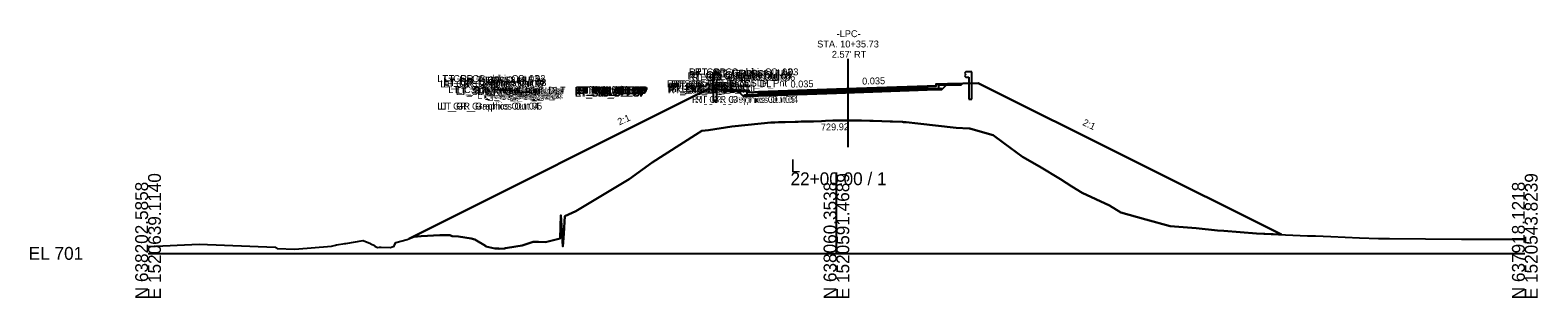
# Model space of a CAD drawing. Extents: x -26 to 3903, y -10 to 9531.
# Drawn here: x 974.3 to 1302.8, y 1990.3 to 2048.6 of the extents above; entities that cross this region are included whole.
import ezdxf

# ---------------------------------------------------------------- set-up
doc = ezdxf.new("R2010")
doc.units = 0
for name, color, linetype in [('Default', 7, 'Continuous'), ('Exist Cross Section Cell', 7, 'Continuous'), ('Exist XS Center Line Elevation Label', 7, 'Continuous'), ('Exist XS Ground Line', 7, 'Continuous'), ('Old_Level_63', 7, 'Continuous'), ('Prop CMT Conc Surface', 7, 'Continuous'), ('Prop CMT Guardrail Graphics', 7, 'Continuous'), ('Prop CMT Pvmt Course 1', 7, 'Continuous'), ('Prop CMT Pvmt Course 1 CG', 7, 'Continuous'), ('Prop CMT Pvmt Course 2', 7, 'Continuous'), ('Prop CMT Pvmt Course 3', 7, 'Continuous'), ('Prop CMT Pvmt Surface', 7, 'Continuous'), ('Prop CMT Slope Grass', 7, 'Continuous'), ('Prop CMT Subgrade Earthwork', 7, 'Continuous'), ('Prop XS Earthwork Shape', 7, 'Continuous'), ('Prop XS Finish Grade Concrete', 7, 'Continuous'), ('Prop XS SE Text', 7, 'Continuous'), ('Prop XS Side Slope Text', 7, 'Continuous')]:
    doc.layers.add(name, color=color, linetype=linetype)

msp = doc.modelspace()

# ---------------------------------------------------------------- linework, layer by layer
at = {"layer": 'Exist Cross Section Cell'}
for p, q in [((1150, 2000), (1150, 2017.66)), ((1000, 2000), (1150, 2000)), ((1150, 2000), (1300, 2000))]:
    msp.add_line(p, q, dxfattribs=at)
at = {"layer": 'Exist XS Ground Line'}
msp.add_lwpolyline([(1000, 2001.52), (1011.14, 2001.98), (1027.72, 2001.34), (1028.14, 2001.07), (1031.96, 2000.89), (1039.99, 2001.56), (1040.83, 2001.78), (1041.03, 2001.83), (1042.86, 2002.16), (1043.11, 2002.18), (1046.84, 2002.77), (1048.5, 2002.18), (1048.53, 2002.1), (1049.34, 2001.7), (1049.43, 2001.58), (1050.03, 2001.3), (1050.43, 2001.36), (1050.8, 2001.34), (1052.8, 2001.26), (1053.22, 2001.4), (1053.66, 2001.58), (1053.77, 2002.01), (1054.01, 2002.34), (1056.48, 2003.06), (1057.92, 2003.64), (1059.52, 2003.78), (1063.59, 2004), (1065.76, 2003.99), (1066.23, 2003.77), (1067.64, 2003.65), (1070.4, 2003.26), (1071.19, 2003.01), (1073.51, 2001.61), (1073.62, 2001.51), (1075.56, 2001.08), (1075.62, 2001.06), (1076.34, 2001.04), (1076.54, 2001.01), (1077.67, 2001.08), (1077.91, 2001.11), (1080.17, 2001.5), (1081.51, 2001.69), (1083.9, 2002.52), (1084.62, 2002.55), (1085.1, 2002.53), (1086.57, 2002.46), (1089.77, 2003.21), (1089.96, 2008.32), (1090.28, 2002.72), (1090.35, 2002.75), (1090.36, 2001.52), (1090.47, 2002.62), (1090.6, 2004.31), (1090.81, 2008.09), (1093.19, 2009.2), (1104.87, 2016.16), (1109.83, 2019.84), (1119.3, 2025.81), (1120.7, 2026.69), (1122.13, 2026.88), (1127.21, 2027.65), (1130.8, 2028.03), (1135.74, 2028.51), (1136.24, 2028.52), (1136.54, 2028.53), (1137.39, 2028.56), (1138.81, 2028.61), (1141.02, 2028.68), (1141.46, 2028.69), (1141.68, 2028.7), (1142.33, 2028.71), (1144.09, 2028.74), (1144.97, 2028.77), (1146.72, 2028.82), (1147.59, 2028.85), (1149.25, 2028.93), (1149.39, 2028.94), (1149.43, 2028.93), (1150.17, 2028.93), (1150.44, 2028.94), (1151.97, 2028.94), (1153.49, 2028.93), (1154.61, 2028.93), (1155.47, 2028.93), (1157.25, 2028.91), (1157.45, 2028.91), (1158.03, 2028.88), (1159.88, 2028.8), (1161.7, 2028.75), (1162.04, 2028.74), (1162.04, 2028.74), (1162.18, 2028.74), (1164.37, 2028.64), (1164.61, 2028.62), (1164.63, 2028.62), (1165.22, 2028.6), (1167.75, 2028.31), (1176.1, 2027.33), (1178.94, 2027.21), (1179.09, 2027.21), (1182.85, 2026.13), (1184.14, 2025.77), (1186.37, 2024.09), (1190.54, 2021.03), (1194.28, 2018.93), (1198.79, 2016.17), (1201.32, 2014.58), (1203.54, 2013.18), (1209.52, 2010.41), (1211.99, 2008.93), (1217.39, 2007.37), (1222.72, 2005.91), (1228.37, 2005.49), (1233.07, 2004.98), (1234.41, 2004.89), (1241.52, 2004.31), (1252.66, 2003.84), (1254.38, 2003.79), (1257.74, 2003.66), (1263.96, 2003.36), (1268.13, 2003.27), (1269.35, 2003.25), (1270.52, 2003.24), (1286.18, 2003.13), (1291.49, 2003.09), (1300, 2003.09)], dxfattribs=at)
at = {"layer": 'Old_Level_63'}
for p, q in [((1171.75, 2036.95), (1171.75, 2036.45)), ((1131, 2035.02), (1131, 2035.52)), ((1133, 2035.17), (1131, 2035.02)), ((1171.75, 2036.45), (1169.75, 2036.46))]:
    msp.add_line(p, q, dxfattribs=at)
for points in [[(1172.25, 2036.95), (1172.25, 2035.96), (1169.75, 2035.87)], [(1177.24, 2036.73), (1177.25, 2037.05)], [(1125.5, 2035.28), (1125.5, 2035.61)], [(1130.5, 2035.18), (1125.5, 2035.28)], [(1130.5, 2035.52), (1130.5, 2034.5), (1133, 2034.59)], [(1130.5, 2035.52), (1130.5, 2035.19)], [(1133, 2034.59), (1133, 2035.17)], [(1169.75, 2035.87), (1169.75, 2036.46)], [(1172.25, 2036.63), (1177.24, 2036.73)]]:
    msp.add_lwpolyline(points, dxfattribs=at)
at = {"layer": 'Prop CMT Conc Surface'}
for points in [[(1121.71, 2036.43), (1121.71, 2036.93), (1122.21, 2036.93)], [(1171.71, 2036.43), (1171.71, 2036.93), (1172.21, 2036.93)], [(1080.47, 2035.51), (1075.47, 2035.61)], [(1080.97, 2035), (1080.97, 2035.5), (1080.47, 2035.5)], [(1082.97, 2035.15), (1080.97, 2035)], [(1119.71, 2036.44), (1121.71, 2036.43)], [(1130.47, 2035.51), (1125.47, 2035.61)], [(1130.97, 2035), (1130.97, 2035.5), (1130.47, 2035.5)], [(1132.97, 2035.15), (1130.97, 2035)], [(1169.71, 2036.44), (1171.71, 2036.43)]]:
    msp.add_lwpolyline(points, dxfattribs=at)
at = {"layer": 'Prop CMT Guardrail Graphics'}
for points in [[(1123.21, 2033.08), (1123.21, 2039.08)], [(1123.21, 2039.08), (1124.54, 2039.08), (1124.81, 2038.78)], [(1124.81, 2038.2), (1124.54, 2037.91), (1123.88, 2037.91)], [(1123.88, 2037.91), (1123.88, 2033.08)], [(1124.81, 2038.78), (1124.54, 2038.49)], [(1124.54, 2038.49), (1124.81, 2038.2)], [(1179.5, 2039.6), (1178.16, 2039.6), (1177.89, 2039.3)], [(1177.89, 2039.3), (1178.16, 2039.01)], [(1178.16, 2039.01), (1177.89, 2038.72)], [(1177.89, 2038.72), (1178.16, 2038.43), (1178.83, 2038.43)], [(1178.83, 2038.43), (1178.83, 2033.6)], [(1179.5, 2033.6), (1179.5, 2039.6)], [(1123.88, 2033.08), (1123.21, 2033.08)], [(1178.83, 2033.6), (1179.5, 2033.6)]]:
    msp.add_lwpolyline(points, dxfattribs=at)
at = {"layer": 'Prop CMT Pvmt Course 1'}
for q in [(1133, 2035.17), (1169.75, 2036.46)]:
    msp.add_line((1150, 2035.76), q, dxfattribs=at)
for points in [[(1133, 2034.92), (1150, 2035.51)], [(1133, 2035.17), (1133, 2034.92)], [(1169.75, 2036.21), (1150, 2035.51)], [(1150, 2035.51), (1150, 2035.76)], [(1150, 2035.51), (1150, 2035.76)], [(1169.75, 2036.46), (1169.75, 2036.21)]]:
    msp.add_lwpolyline(points, dxfattribs=at)
msp.add_lwpolyline([(1150, 2035.51), (1150, 2035.64), (1150, 2035.64), (1150, 2035.51)], close=True, dxfattribs=at)
msp.add_lwpolyline([(1150, 2035.51), (1150, 2035.64), (1150, 2035.64), (1150, 2035.51)], close=True, dxfattribs=at)
at = {"layer": 'Prop CMT Pvmt Course 1 CG'}
for points in [[(1133, 2034.59), (1130, 2034.48), (1129.74, 2034.22)], [(1129.74, 2034.22), (1133, 2034.34)], [(1133, 2034.34), (1133, 2034.59)], [(1169.75, 2035.87), (1172.75, 2035.98), (1172.99, 2035.74)], [(1169.75, 2035.62), (1169.75, 2035.87)], [(1172.99, 2035.74), (1169.75, 2035.62)]]:
    msp.add_lwpolyline(points, dxfattribs=at)
at = {"layer": 'Prop CMT Pvmt Course 2'}
for points in [[(1150, 2035.51), (1133, 2034.92)], [(1133, 2034.59), (1150, 2035.18)], [(1133, 2034.92), (1133, 2034.59)], [(1150, 2035.51), (1169.75, 2036.21)], [(1169.75, 2035.87), (1150, 2035.18)], [(1150, 2035.18), (1150, 2035.51)], [(1150, 2035.18), (1150, 2035.51)], [(1169.75, 2036.21), (1169.75, 2035.87)]]:
    msp.add_lwpolyline(points, dxfattribs=at)
at = {"layer": 'Prop CMT Pvmt Course 3'}
for points in [[(1150, 2035.18), (1133, 2034.59)], [(1133, 2034.34), (1150, 2034.93)], [(1133, 2034.59), (1133, 2034.34)], [(1150, 2035.18), (1169.75, 2035.87)], [(1169.75, 2035.62), (1150, 2034.93)], [(1150, 2034.93), (1150, 2035.18)], [(1150, 2034.93), (1150, 2035.18)], [(1169.75, 2035.87), (1169.75, 2035.62)]]:
    msp.add_lwpolyline(points, dxfattribs=at)
at = {"layer": 'Prop CMT Pvmt Surface'}
for p, q in [((1150, 2035.76), (1133, 2035.17)), ((1169.75, 2036.46), (1150, 2035.76))]:
    msp.add_line(p, q, dxfattribs=at)
for points in [[(1150, 2035.76), (1133, 2035.17)], [(1150, 2035.76), (1169.75, 2036.46)]]:
    msp.add_lwpolyline(points, dxfattribs=at)
at = {"layer": 'Prop CMT Slope Grass'}
msp.add_line((1180.89, 2037.12), (1246.97, 2004.08), dxfattribs=at)
for points in [[(1172.25, 2036.95), (1180.89, 2037.12)], [(1121.81, 2035.7), (1056.82, 2003.2)], [(1130.5, 2035.52), (1121.81, 2035.69)]]:
    msp.add_lwpolyline(points, dxfattribs=at)
at = {"layer": 'Prop CMT Subgrade Earthwork'}
for points in [[(1169.75, 2035.62), (1172.99, 2035.74), (1174.24, 2036.99)], [(1133, 2034.34), (1129.74, 2034.22), (1128.4, 2035.56)], [(1150, 2034.93), (1133, 2034.34)], [(1150, 2034.93), (1169.75, 2035.62)]]:
    msp.add_lwpolyline(points, dxfattribs=at)
at = {"layer": 'Prop XS Earthwork Shape'}
for points in [[(1172.99, 2035.74), (1174.22, 2036.97), (1180.89, 2037.12), (1246.97, 2004.08), (1241.52, 2004.31), (1234.41, 2004.89), (1233.07, 2004.98), (1228.37, 2005.49), (1222.72, 2005.91), (1217.39, 2007.37), (1211.99, 2008.93), (1209.52, 2010.41), (1203.54, 2013.18), (1201.32, 2014.58), (1198.79, 2016.17), (1194.28, 2018.93), (1190.54, 2021.03), (1186.37, 2024.09), (1184.14, 2025.77), (1182.85, 2026.13), (1179.09, 2027.21), (1178.94, 2027.21), (1176.1, 2027.33), (1167.75, 2028.31), (1165.22, 2028.6), (1164.63, 2028.62), (1164.37, 2028.64), (1162.18, 2028.74), (1162.04, 2028.74), (1161.7, 2028.75), (1159.88, 2028.8), (1158.03, 2028.88), (1157.45, 2028.91), (1157.25, 2028.91), (1155.47, 2028.93), (1154.61, 2028.93), (1153.49, 2028.93), (1151.97, 2028.94), (1150.44, 2028.94), (1150.17, 2028.93), (1149.43, 2028.93), (1149.25, 2028.93), (1147.59, 2028.85), (1146.72, 2028.82), (1144.97, 2028.77), (1144.09, 2028.74), (1142.33, 2028.71), (1141.68, 2028.7), (1141.46, 2028.69), (1141.02, 2028.68), (1138.81, 2028.61), (1137.39, 2028.56), (1136.54, 2028.53), (1136.24, 2028.52), (1135.74, 2028.51), (1130.8, 2028.03), (1127.21, 2027.65), (1122.13, 2026.88), (1120.7, 2026.69), (1119.3, 2025.81), (1109.83, 2019.84), (1104.87, 2016.16), (1093.19, 2009.2), (1090.81, 2008.09), (1090.6, 2004.31), (1090.36, 2001.52), (1090.28, 2002.72), (1089.96, 2008.32), (1089.77, 2003.21), (1086.57, 2002.46), (1085.1, 2002.53), (1084.62, 2002.55), (1083.9, 2002.52), (1081.51, 2001.69), (1080.17, 2001.5), (1077.91, 2001.11), (1077.67, 2001.08), (1076.54, 2001.01), (1076.34, 2001.04), (1075.56, 2001.08), (1073.62, 2001.51), (1073.51, 2001.61), (1071.19, 2003.01), (1070.4, 2003.26), (1067.64, 2003.65), (1066.23, 2003.77), (1065.76, 2003.99), (1063.59, 2004), (1059.52, 2003.78), (1057.92, 2003.64), (1056.82, 2003.2), (1121.81, 2035.7), (1125.47, 2035.61), (1128.42, 2035.55), (1129.74, 2034.22), (1133, 2034.34), (1150, 2034.93), (1169.75, 2035.62)], [(1150, 2034.93), (1133, 2034.34), (1129.74, 2034.22), (1128.42, 2035.55), (1125.47, 2035.61), (1121.81, 2035.7), (1056.82, 2003.2), (1057.92, 2003.64), (1059.52, 2003.78), (1063.59, 2004), (1065.76, 2003.99), (1066.23, 2003.77), (1067.64, 2003.65), (1070.4, 2003.26), (1071.19, 2003.01), (1073.51, 2001.61), (1073.62, 2001.51), (1075.56, 2001.08), (1076.34, 2001.04), (1076.54, 2001.01), (1077.67, 2001.08), (1077.91, 2001.11), (1080.17, 2001.5), (1081.51, 2001.69), (1083.9, 2002.52), (1084.62, 2002.55), (1085.1, 2002.53), (1086.57, 2002.46), (1089.77, 2003.21), (1089.96, 2008.32), (1090.28, 2002.72), (1090.36, 2001.52), (1090.6, 2004.31), (1090.81, 2008.09), (1093.19, 2009.2), (1104.87, 2016.16), (1109.83, 2019.84), (1119.3, 2025.81), (1120.7, 2026.69), (1122.13, 2026.88), (1127.21, 2027.65), (1130.8, 2028.03), (1135.74, 2028.51), (1136.24, 2028.52), (1136.54, 2028.53), (1137.39, 2028.56), (1138.81, 2028.61), (1141.02, 2028.68), (1141.46, 2028.69), (1141.68, 2028.7), (1142.33, 2028.71), (1144.09, 2028.74), (1144.97, 2028.77), (1146.72, 2028.82), (1147.59, 2028.85), (1149.25, 2028.93), (1149.43, 2028.93), (1150.17, 2028.93), (1150.44, 2028.94), (1151.97, 2028.94), (1153.49, 2028.93), (1154.61, 2028.93), (1155.47, 2028.93), (1157.25, 2028.91), (1157.45, 2028.91), (1158.03, 2028.88), (1159.88, 2028.8), (1161.7, 2028.75), (1162.04, 2028.74), (1162.18, 2028.74), (1164.37, 2028.64), (1164.63, 2028.62), (1165.22, 2028.6), (1167.75, 2028.31), (1176.1, 2027.33), (1178.94, 2027.21), (1179.09, 2027.21), (1182.85, 2026.13), (1184.14, 2025.77), (1186.37, 2024.09), (1190.54, 2021.03), (1194.28, 2018.93), (1198.79, 2016.17), (1201.32, 2014.58), (1203.54, 2013.18), (1209.52, 2010.41), (1211.99, 2008.93), (1217.39, 2007.37), (1222.72, 2005.91), (1228.37, 2005.49), (1233.07, 2004.98), (1234.41, 2004.89), (1241.52, 2004.31), (1246.97, 2004.08), (1180.89, 2037.12), (1174.22, 2036.97), (1172.99, 2035.74), (1169.75, 2035.62)]]:
    msp.add_lwpolyline(points, close=True, dxfattribs=at)
at = {"layer": 'Prop XS Finish Grade Concrete'}
for points in [[(1169.75, 2036.46), (1171.75, 2036.45), (1171.75, 2036.95), (1172.25, 2036.95)], [(1133, 2035.17), (1131, 2035.02), (1131, 2035.52), (1130.5, 2035.52)]]:
    msp.add_lwpolyline(points, dxfattribs=at)
at = {"layer": 'Prop XS SE Text'}
msp.add_line((1152.57, 2023.13), (1152.57, 2042.42), dxfattribs=at)

# ---------------------------------------------------------------- texts
at = {"layer": 'Default'}
msp.add_text('-', height=0.0001, dxfattribs=at).set_placement((1000.03, 2000.02))
at = {"layer": 'Exist Cross Section Cell'}
for s, p in [('E 1520639.1140', (1002.8, 1990)), ('E 1520591.4689', (1152.8, 1990)), ('E 1520543.8239', (1302.8, 1990)), ('N 638202.5858', (1000, 1990)), ('N 638060.3538', (1150, 1990)), ('N 637918.1218', (1300, 1990))]:
    msp.add_text(s, height=2.8, rotation=90, dxfattribs=at).set_placement(p)
for s, p in [('22+00.00 / 1', (1140, 2014.86)), ('L', (1140, 2017.66)), ('EL 701', (974, 1998.6))]:
    msp.add_text(s, height=2.8, dxfattribs=at).set_placement(p)
at = {"layer": 'Exist XS Center Line Elevation Label'}
msp.add_text('729.92', height=1.5, rotation=0.8401, dxfattribs=at).set_placement((1146.61, 2026.77))
at = {"layer": 'Prop CMT Conc Surface'}
for s, p in [('RT_GR_Graphics Out 02', (1117.88, 2038.8)), ('RT_GR_Graphics Out 03', (1119.19, 2038.8)), ('LT_GR_Graphics Out 03', (1063.04, 2037.35)), ('LT_GR_Graphics Out 06', (1063.68, 2036.19)), ('LT_GR_Graphics Out 07', (1064.33, 2036.19)), ('LT_GR_Graphics Out 09', (1064.35, 2036.77)), ('LT_GR_Graphics Out 02', (1064.39, 2037.35)), ('LT_GR_Graphics Out 08', (1064.62, 2036.48)), ('LT_GR_Out', (1070.47, 2037.06)), ('RT_Sub_Trench_Out_DLT', (1113.09, 2036.22)), ('RT_PV2_OEOT', (1113.24, 2035.44)), ('RT_PV1_OEOT', (1113.42, 2035.69)), ('RT_CG_Top_Face', (1114.01, 2036.18)), ('RT_CG_Top_Gut', (1114.4, 2035.68)), ('RT_CG_Top_BOC', (1114.48, 2036.18)), ('RT_GR_Graphics Out 08', (1117.56, 2037.93)), ('RT_GR_Graphics Out 07', (1117.82, 2037.64)), ('RT_GR_Graphics Out 09', (1117.84, 2038.22)), ('RT_GR_Graphics Out 06', (1118.5, 2037.64)), ('RT_GR_Out', (1123.42, 2038.51)), ('RT_CSLP_Pnt', (1126.07, 2036.37)), ('LT_CSLP_Pnt', (1065.42, 2034.94)), ('LT_SDWK_Out_Top', (1066.91, 2034.86)), ('LT_SDWK_Out_Bot', (1067.09, 2034.53)), ('LT_Sub_Trench_Out_DLT', (1067.35, 2034.8)), ('LT_CG1_Shelf_Out', (1071.7, 2033.72)), ('LT_SDWK_In_Top', (1072.78, 2034.76)), ('LT_CG_Top_BOC', (1072.83, 2034.75)), ('LT_SDWK_In_Bot', (1072.96, 2034.43)), ('LT_CG_Bot_BOC', (1073.04, 2033.73)), ('LT_CG_Top_Face', (1073.35, 2034.75)), ('LT_Sub_OEOP', (1073.36, 2033.46)), ('LT_CG_Top_Gut', (1073.75, 2034.25)), ('LT_PV2_OEOT', (1076.59, 2034.15)), ('LT_PV3_OEOT', (1076.59, 2033.82)), ('LT_Sub_OEOT', (1076.62, 2033.57)), ('LT_PV1_OEOT', (1076.77, 2034.4)), ('LT_CG_Bot_IE', (1076.85, 2033.82)), ('RT_PV2_OEEOP', (1092.97, 2034.75)), ('RT_PV3_OEEOP', (1092.97, 2034.41)), ('RT_Sub_OEEOP', (1093, 2034.16)), ('LT_PV2_OEEOP', (1093.06, 2034.75)), ('LT_PV3_OEEOP', (1093.06, 2034.41)), ('LT_Sub_OEEOP', (1093.09, 2034.16)), ('RT_PV1_OEEOP', (1093.15, 2034.87)), ('LT_PV1_OEEOP', (1093.23, 2034.87)), ('RT_PV2_IEEOP', (1093.54, 2034.75)), ('LT_PV2_IEEOP', (1093.63, 2034.75)), ('RT_PV1_IEEOP', (1093.72, 2034.87)), ('LT_PV1_IEEOP', (1093.81, 2034.87)), ('PV2_PGL', (1095.99, 2034.75)), ('PV1_PGL', (1096.17, 2035)), ('RT_PV3_OEOT', (1113.24, 2035.11)), ('RT_Sub_OEOT', (1113.28, 2034.86)), ('RT_CG_Bot_IE', (1113.5, 2035.11)), ('RT_CG1_Shelf_Out', (1114.36, 2035.21)), ('RT_CG_Bot_BOC', (1114.69, 2035.19)), ('RT_Sub_OEOP', (1116.51, 2034.97)), ('RT_GR_Graphics Out 05', (1118.51, 2032.8)), ('RT_GR_Graphics Out 04', (1119.17, 2032.8)), ('LT_GR_Graphics Out 04', (1063.01, 2031.35)), ('LT_GR_Graphics Out 05', (1063.69, 2031.35))]:
    msp.add_text(s, height=1.5, dxfattribs=at).set_placement(p)
at = {"layer": 'Prop XS SE Text'}
for s, rotation, p in [('-LPC-', 359.9946, (1150.04, 2047.13)), ('STA. 10+35.73 ', 359.9946, (1145.8, 2044.88)), ("2.57' RT", 359.9946, (1148.99, 2042.63)), ('0.035', 1.1458, (1140, 2036.12)), ('0.035', 1.1458, (1155.61, 2036.78))]:
    msp.add_text(s, height=1.5, rotation=rotation, dxfattribs=at).set_placement(p)
at = {"layer": 'Prop XS Side Slope Text'}
for rotation, p in [(23.9099, (1102.69, 2027.89)), (334.8977, (1203.49, 2028.02))]:
    msp.add_text('2:1', height=1.5, rotation=rotation, dxfattribs=at).set_placement(p)

doc.saveas('drawing.dxf')
